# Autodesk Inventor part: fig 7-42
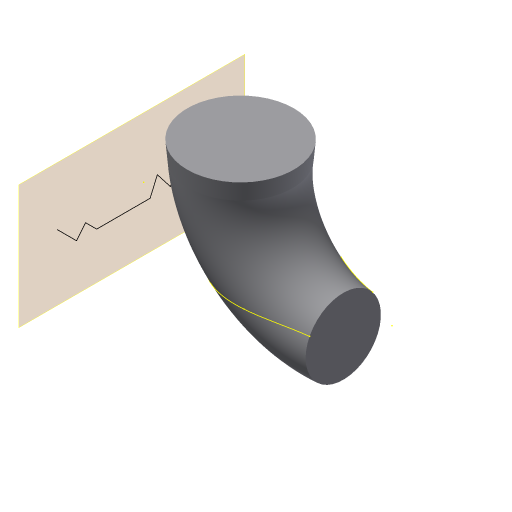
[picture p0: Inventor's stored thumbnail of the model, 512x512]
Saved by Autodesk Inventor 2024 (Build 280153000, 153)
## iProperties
Created: 2011-07
Part Number: fig 7-42
Material: Generic
Document SubType Name: Modeling
Designer: CadCim
Density: 1 g/cm^3
Appearance: Default
Author: CadCim
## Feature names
1. Sweep1
## Parameters: d0 = 5 deg, d1 = -14.75 mm, d2 = 0
